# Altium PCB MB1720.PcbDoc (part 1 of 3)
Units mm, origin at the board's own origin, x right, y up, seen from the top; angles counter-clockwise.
Board outline 62.4 x 34.09 mm, 4 copper layers (Top Layer, MidLayer 1, MidLayer 2, Bottom Layer), stack 1.594 mm thick; 82 components, 66 nets, 241 pads, 1258 vias.
Unrouted connection lines stored in the file: 1.
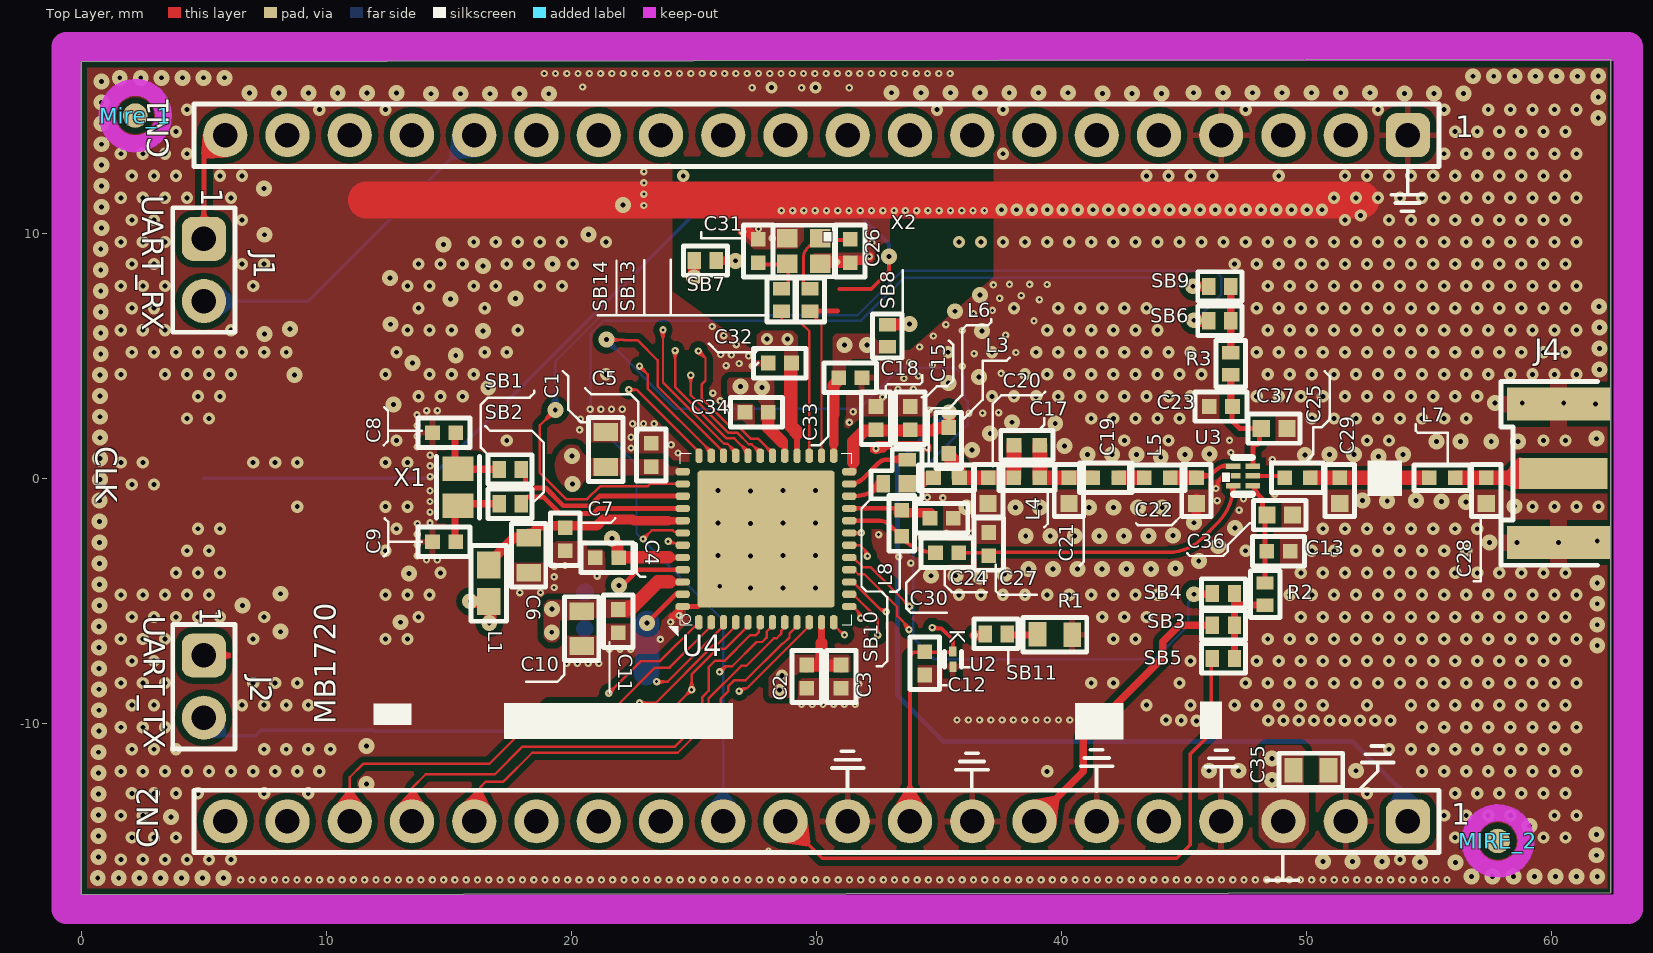
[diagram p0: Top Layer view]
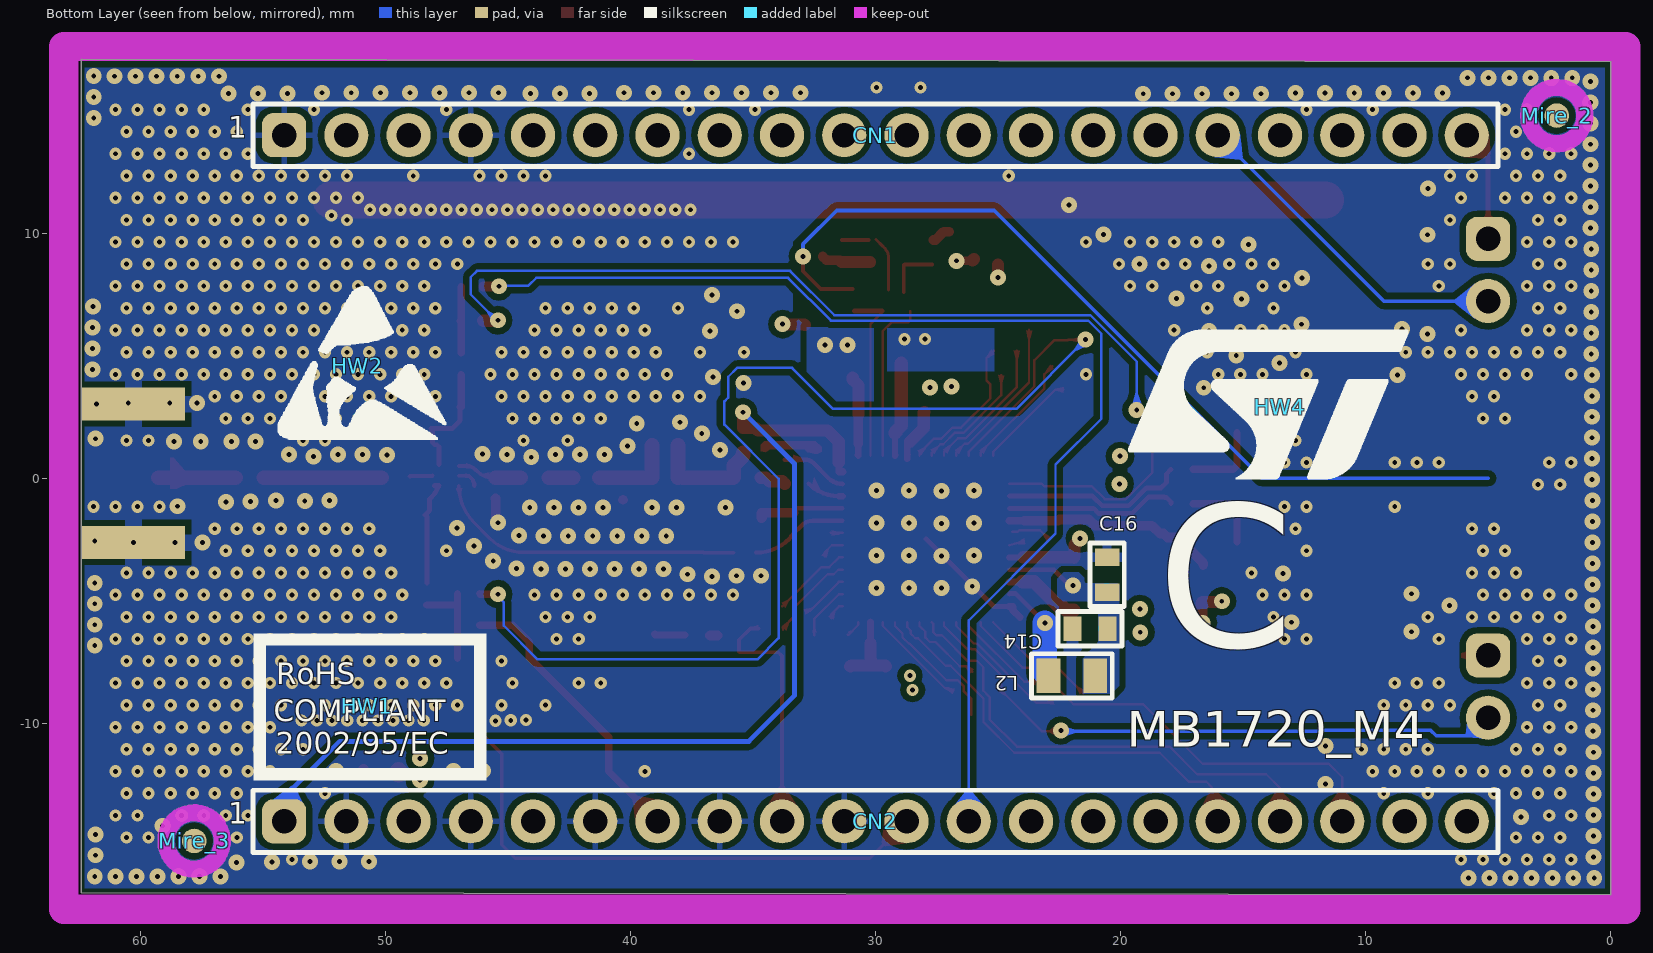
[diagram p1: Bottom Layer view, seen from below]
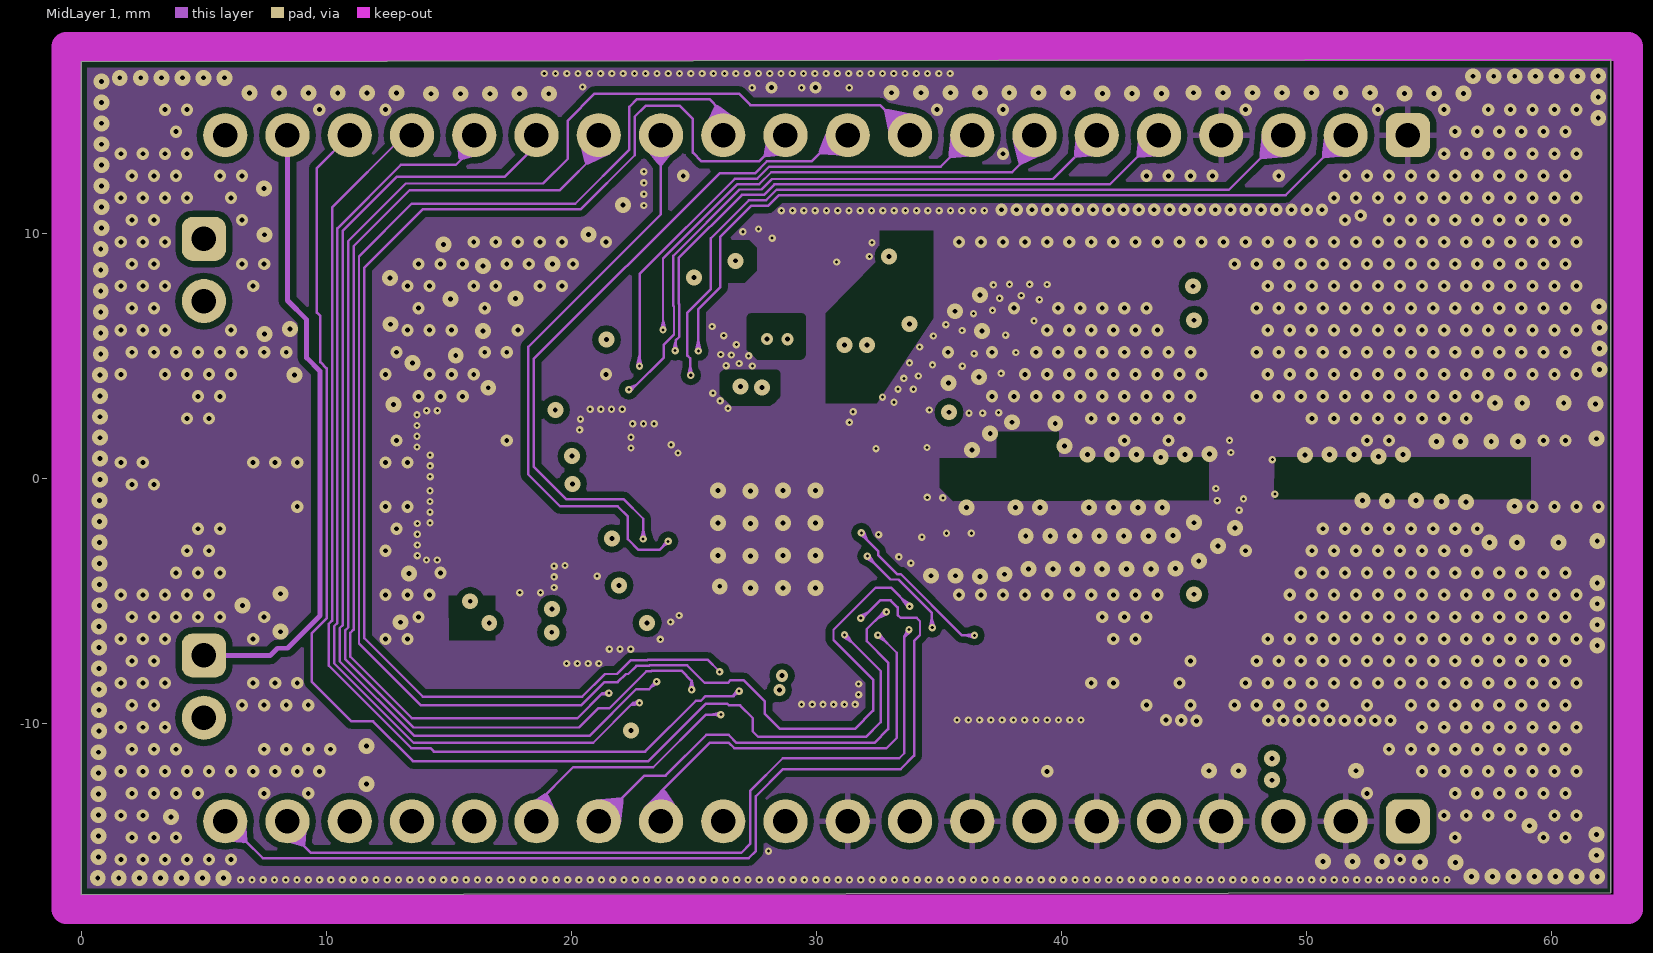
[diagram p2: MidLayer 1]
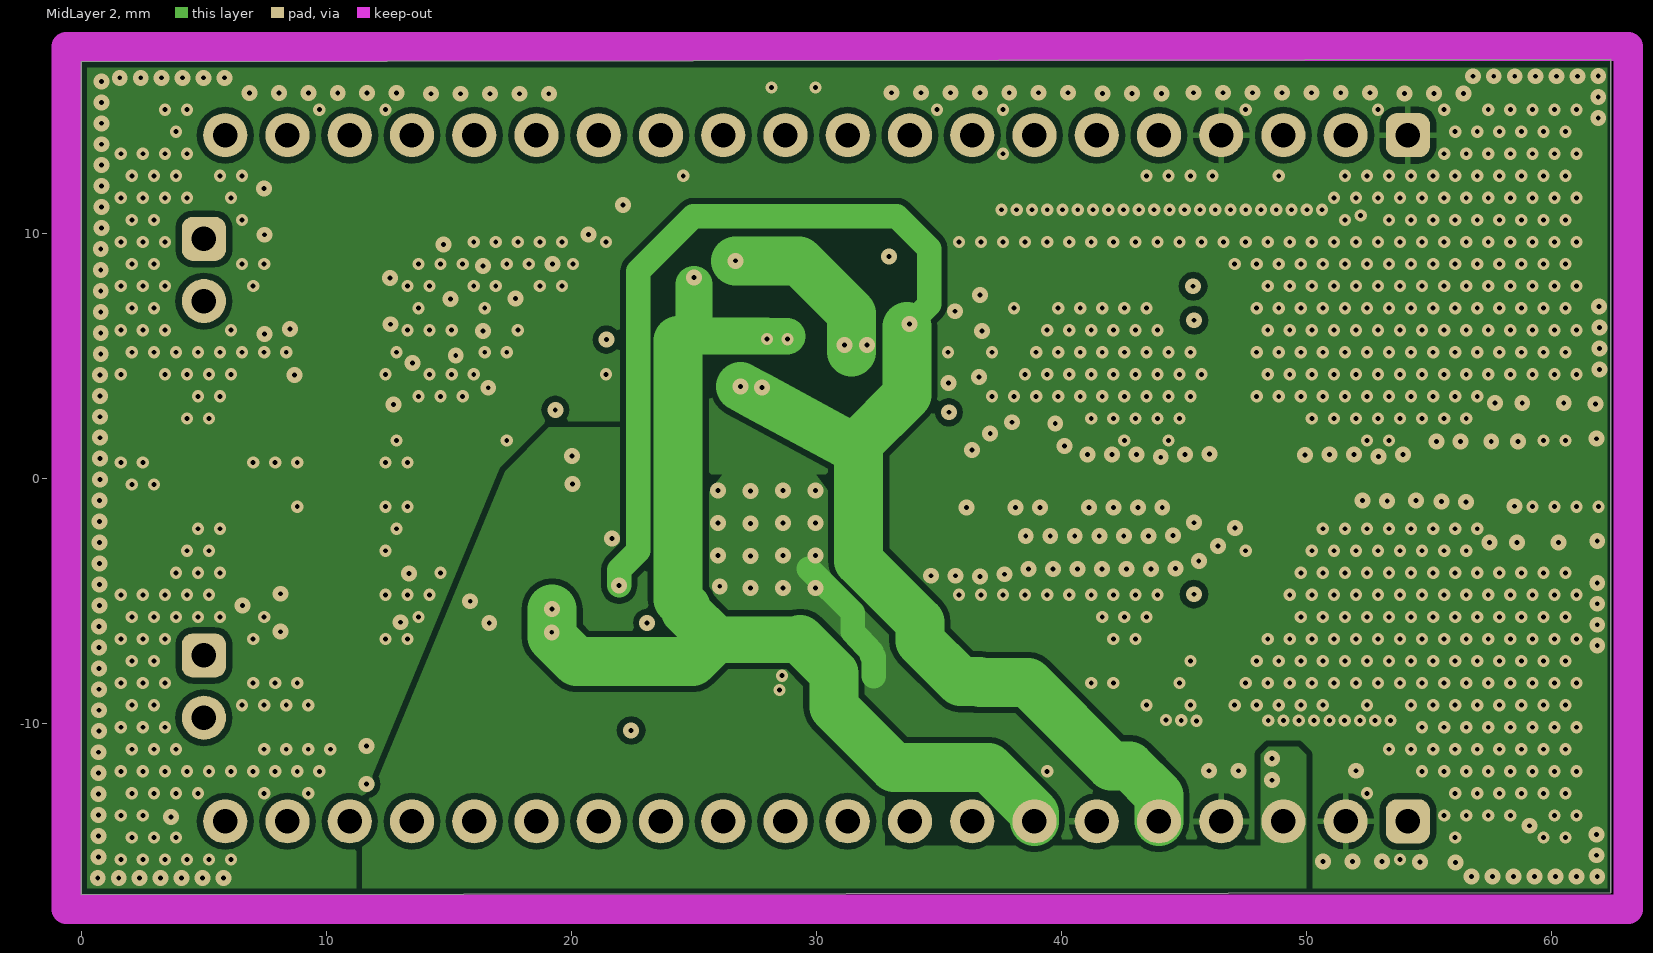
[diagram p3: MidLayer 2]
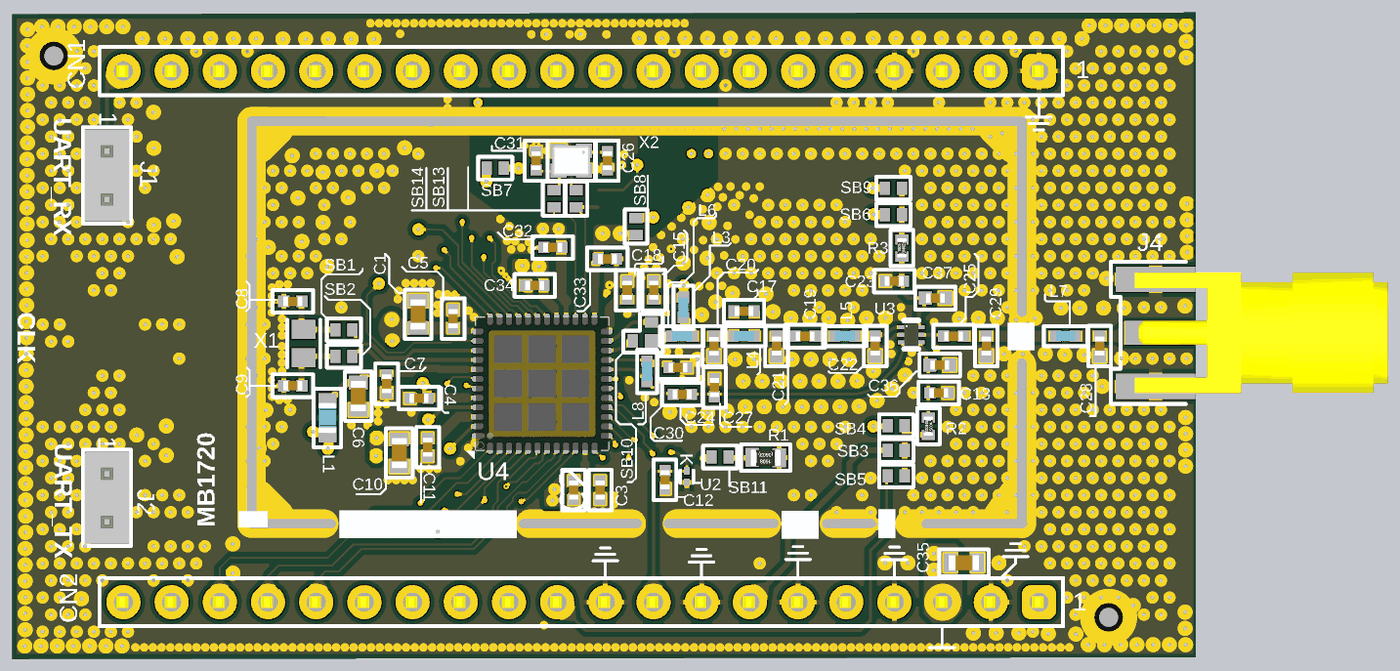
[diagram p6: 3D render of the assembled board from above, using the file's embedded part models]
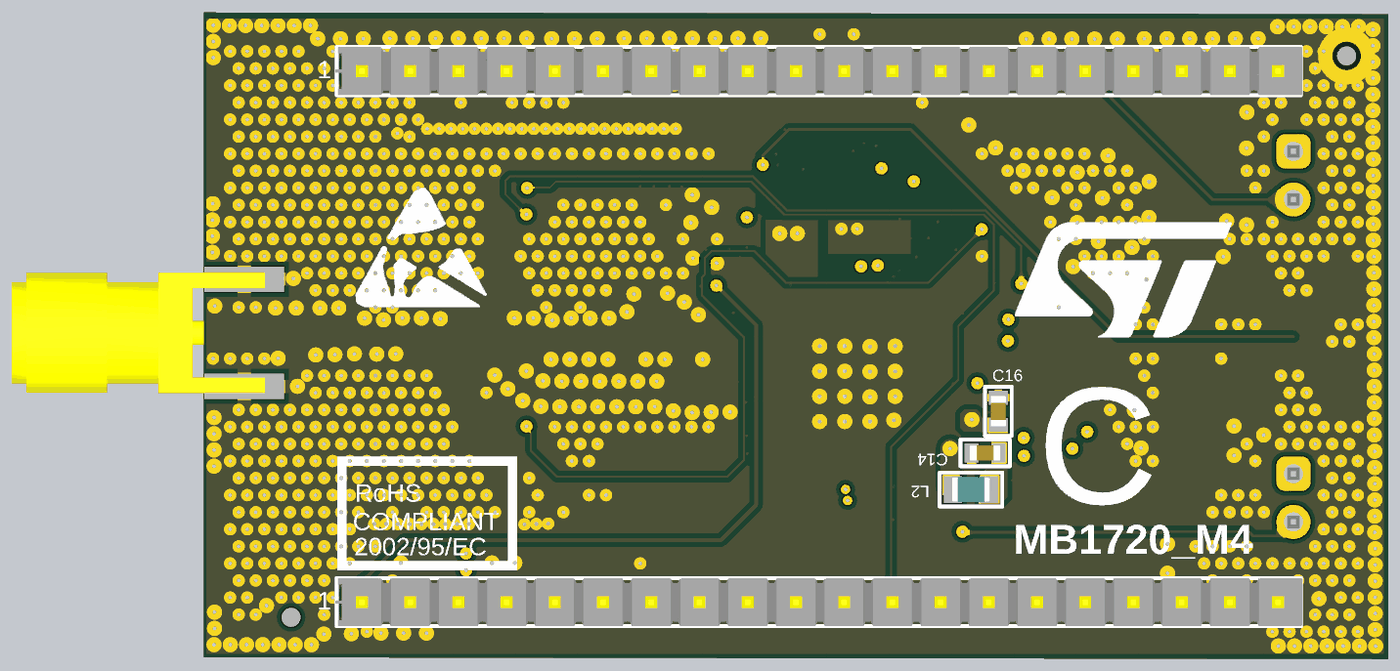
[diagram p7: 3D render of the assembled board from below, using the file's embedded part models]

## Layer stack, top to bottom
Top Solder: solder mask 0.02, Solder Resist, Dk 3.5
Top Layer: signal copper 0.054
Dielectric 1: prepreg 0.108, 1 X 2116, Dk 3.6
MidLayer 1: signal copper 0.035
Dielectric 2: core 1.2, FR4 TG135, Dk 4.7
MidLayer 2: signal copper 0.035
Dielectric 3: prepreg 0.108, 1 X 2116, Dk 3.6
Bottom Layer: signal copper 0.054
Bottom Solder: solder mask 0.02, Solder Resist, Dk 3.5

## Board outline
0,-17 0,17 62.401,17.093 62.401,-16.907

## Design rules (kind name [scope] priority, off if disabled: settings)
BoardOutlineClearance [All] p1 off: gap=0.6 ignorepadtopadclearanceinfootprint=FALSE
Clearance Clearance_2 [InNetClass('50Ohms')] p1: gap=0.19 ignorepadtopadclearanceinfootprint=TRUE except(0.14: SMDPad-Region; 0.15: SMDPad-SMDPad; 0.17: Track-SMDPad; 0.18: Track-Poly)
Clearance Clearance_1 [OnLayer('MidLayer 1')       and InPolygon vs All    and WithinRoom('RoomDefinition_BGA')] p2: gap=0.146 ignorepadtopadclearanceinfootprint=TRUE
Clearance Clearance_tab [(ObjectKind = 'Pad') And (Name Like 'Tab*-*') vs OnLayer('Keep-Out Layer')] p3: gap=0 ignorepadtopadclearanceinfootprint=TRUE
Clearance Clearance_Via_BGA [TouchesRoom('RoomDefinition_BGA') vs isvia or ispad or istrack] p4: gap=0.085 ignorepadtopadclearanceinfootprint=TRUE except(0.15: Arc-Region Track-Region SMDPad-Region THPad-Region Via-Region Region-Region; 0.25: Arc-Fill Arc-Poly Track-Fill Track-Poly SMDPad-Fill SMDPad-Poly THPad-Fill THPad-Poly Via-Fill Via-Poly Fill-Fill Fill-Poly Fill-Region Fill-Text Fill-Hole Poly-Poly Poly-Region Poly-Text Poly-Hole Region-Text Region-Hole)
Clearance Clearance_via_to_via [(ObjectKind = 'Via') And (Net <> 'GND') vs (ObjectKind = 'Via') And (Net <> 'GND')] p5: gap=0.65 ignorepadtopadclearanceinfootprint=TRUE
Clearance "Clearance_Polygon to All" [InPolygon] p6: gap=0.25 ignorepadtopadclearanceinfootprint=TRUE
Clearance [All] p7: gap=0.12 ignorepadtopadclearanceinfootprint=TRUE except(0.25: Arc-Via Track-Via SMDPad-Via THPad-Via Via-Fill Via-Poly Via-Region)
ComponentClearance [All] p1: gap=0 collisioncheckmode=3 verticalgap=0.1 showdistances=FALSE
DiffPairsRouting [InDifferentialPair('RFI')] p1: maxlimit=0.165 minlimit=0.165 mostfreqgap=0.165 toplayer_minwidth=0.08 toplayer_maxwidth=0.4 toplayer_prefwidth=0.145 midlayer1_minwidth=0.145 midlayer1_maxwidth=0.145 midlayer1_prefwidth=0.145 midlayer2_minwidth=0.145 midlayer2_maxwidth=0.145 midlayer2_prefwidth=0.145 bottomlayer_minwidth=0.145 bottomlayer_maxwidth=0.145 bottomlayer_prefwidth=0.145 maxuncoupledlength=12.7
HoleSize [All] p1: absolutevalues=TRUE maxlimit=10 minlimit=0.025 maxpercent=80.000 minpercent=20.000
MaximumViaCount [All] p1: limit=3
MinimumSolderMaskSliver [All] p1: minsoldermaskwidth=0.1
PlaneConnect [InNet('GND')] p1: planeconnectstyle=Relief reliefexpansion=0.508 reliefentries=4 reliefconductorwidth=0.21 reliefairgap=0.21
PolygonConnect PolygonConnect_6 [InNet('VDDRF1V55')] p1: connectstyle=Direct reliefconductorwidth=0.254 reliefentries=4 polygonreliefangle="90 Angle" airgapwidth=0.254
PolygonConnect PolygonConnect_5 [InNet('VDDRF1V55')] p2: connectstyle=Direct reliefconductorwidth=0.254 reliefentries=4 polygonreliefangle="90 Angle" airgapwidth=0.254
PolygonConnect PolygonConnect_4 [InNet('vDDRF')] p3: connectstyle=Direct reliefconductorwidth=0.254 reliefentries=4 polygonreliefangle="90 Angle" airgapwidth=0.254
PolygonConnect PolygonConnect_3 [InNet('VDDPA')] p4: connectstyle=Direct reliefconductorwidth=0.254 reliefentries=4 polygonreliefangle="90 Angle" airgapwidth=0.254
PolygonConnect PolygonConnect_1 [InNet('VDDRF1V55')] p5: connectstyle=Direct reliefconductorwidth=0.254 reliefentries=4 polygonreliefangle="90 Angle" airgapwidth=0.254
PolygonConnect [InNet('VDD')] p6: connectstyle=Direct reliefconductorwidth=0.254 reliefentries=4 polygonreliefangle="90 Angle" airgapwidth=0.254
PolygonConnect PolygonConnect_VRPA [InNet('VRPA')] p7: connectstyle=Direct reliefconductorwidth=0.254 reliefentries=4 polygonreliefangle="90 Angle" airgapwidth=0.254
PolygonConnect PolygonConnect_RF [(ObjectKind = 'Pad') And (Name = 'C30-1')           or (ObjectKind = 'Pad') And (Name = 'C27-1')] p8: connectstyle=Direct reliefconductorwidth=0.254 reliefentries=4 polygonreliefangle="90 Angle" airgapwidth=0.254
PolygonConnect PolygonConnect_J1 [(ObjectKind = 'Pad') And (Name = 'J1-2')] p9: connectstyle=Direct reliefconductorwidth=0.254 reliefentries=4 polygonreliefangle="90 Angle" airgapwidth=0.254
PolygonConnect PolygonConnect_All [All] p10: thpad.connectstyle=Relief thpad.reliefconductorwidth=0.25 thpad.reliefentries=4 thpad.polygonreliefangle="90 Angle" thpad.airgapwidth=0.25 smdpad.connectstyle=Relief smdpad.reliefconductorwidth=0.25 smdpad.reliefentries=4 smdpad.polygonreliefangle="90 Angle" smdpad.airgapwidth=0.25 via.connectstyle=Direct via.reliefconductorwidth=0.2 via.reliefentries=4 via.polygonreliefangle="90 Angle" via.airgapwidth=0.25
RoutingLayers "RoutingLayers_90 Ohms" [InDifferentialPairClass('All Differential Pairs')] p1: top layer_v5=TRUE mid layer 1_v5=TRUE mid layer 2_v5=TRUE bottom layer_v5=TRUE
RoutingLayers [All] p2: top layer_v5=TRUE mid layer 1_v5=TRUE mid layer 2_v5=TRUE bottom layer_v5=TRUE
RoutingVias RoutingVias_BGA [InDrillLayerPair('Top Layer - MidLayer 1')] p1: holewidth=0.125 width=0.25 viastyle="Through Hole" minholewidth=0.125 minwidth=0.25 maxholewidth=0.125 maxwidth=0.3
RoutingVias [All] p2: holewidth=0.2 width=0.65 viastyle="Through Hole" minholewidth=0.2 minwidth=0.5 maxholewidth=0.2 maxwidth=0.65
ShortCircuit [(ObjectKind = 'Via') And (DrillPair = 'Top Layer - MidLayer 1') vs Ispad] p1: allowed=TRUE
SilkToSilkClearance [All] p1: silktosilkclearance=0.2
SilkToSolderMaskClearance [IsPad] p1: minsilkscreentomaskgap=0.2 clearancetoexposedcopper=TRUE
SolderMaskExpansion SolderMaskExpansion_VIA [IsVia] p1: expansion=-0.2 istentingtop=FALSE
SolderMaskExpansion [All] p2: expansion=0.075 istentingtop=FALSE
Width Width_BGA [OnLayer('Top Layer')      and WithinRoom('RoomDefinition_BGA')] p1: maxlimit=0.08 minlimit=0.08 preferedwidth=0.08 minimp=50.000000 maximp=50.000000 favimp=50.000000
Width Width_50Ohms [InNetClass('50Ohms')] p2: maxlimit=0.7 minlimit=0.097 preferedwidth=0.5 toplayer_minwidth=0.14 midlayer1_maxwidth=0.5 midlayer2_minwidth=0.2 midlayer2_maxwidth=0.5 bottomlayer_minwidth=0.2 bottomlayer_maxwidth=0.5 minimp=50.000000 maximp=50.000000 favimp=50.000000
Width [All] p3: maxlimit=2 minlimit=0.08 preferedwidth=0.15 toplayer_minwidth=0.097 toplayer_maxwidth=1.5 midlayer1_maxwidth=1 midlayer2_minwidth=0.1 bottomlayer_minwidth=0.1 bottomlayer_maxwidth=1.5 minimp=50.000000 maximp=50.000000 favimp=50.000000
21 further rules are at their usual default settings.

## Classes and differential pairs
net class 50Ohms: NetC17_1 NetC17_2 NetC19_1 NetC22_2 NetC24_2 NetC25_1 NetC25_2 NetC28_1 NetL6_2 NetSB10_1 NetSB10_3
component class BEE_UFQFPN48_Ref_Board: C1 C2 C3 C4 C5 C6 C7 C8 C9 C10 C11 C12 C13 C14 C15 C16 C17 C18 C19 C20 C21 C22 C23 C24 C25 C26 C27 C28 C29 C30 C31 C32 C33 C34 C35 C36 C37 CN1 CN2 J1 J2 J4 L1 L2 L3 L4 L5 L6 L7 L8 R1 R2 R3 SB1 SB2 SB3 SB4 SB5 SB6 SB7 SB8 SB9 SB10 SB11 SB13 SB14 U2 U3 U4 X1 X2
differential pair RFI: +RFI_P -RFI_N

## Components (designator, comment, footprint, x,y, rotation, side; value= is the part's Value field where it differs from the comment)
C1 "" CAPC1608X09N 21.4,1.175 r270 top value=4.7uF
C2 "" CAPC1005X06N 29.6,-8.09 r90 top value=100nF
C3 "" CAPC1005X06N 31,-8.09 r90 top value=100nF
C4 "" CAPC1005X06N 21.449,-3.241 r0 top value=100nF
C5 "" CAPC1005X06N 23.251,0.95 r270 top value=100nF
C6 "" CAPC1608X09N 18.249,-3.139 r270 top value=4.7uF
C7 "" CAPC1005X06N 19.749,-2.488 r270 top value=100nF
C8 "Capacitor" CAPC1005X06N 14.798,1.862 r180 top value=6.8pF
C9 "Capacitor" CAPC1005X06N 14.798,-2.589 r180 top value=6.8pF
C10 "" CAPC1608X09N 20.411,-6.134 r270 top value=4.7uF
C11 "" CAPC1005X06N 21.911,-5.832 r270 top value=100nF
C12 "" CAPC1005X06N 34.413,-7.549 r270 top value=100nF
C13 "" CAPC1005X06N 48.847,-2.973 r180 top value=1nF
C14 "" CAPC1608X09N 21.243,-6.136 r0 bottom value="0.47 uF"
C15 "" CAPC1005X06N 33.823,2.45 r90 top value="47 nF"
C16 "" CAPC1608X09N 20.546,-3.936 r90 bottom value="100 nF"
C17 "" "CAPC1005X06N - DUPLICATE - DUPLICATE"#1 38.581,1.345 r0 top value="3.6 pF"
C18 "" CAPC1005X06N 32.423,2.45 r270 top value="68 pF"
C19 "" "CAPC1005X06N - DUPLICATE - DUPLICATE"#1 41.799,0.025 r180 top value="68 pF"
C20 "" "CAPC1005X06N - DUPLICATE - DUPLICATE"#2 37,-0.505 r270 top value=N/C
C21 "" "CAPC1005X06N - DUPLICATE - DUPLICATE"#3 40.299,-0.5 r90 top value="15 pF"
C22 "" "CAPC1005X06N - DUPLICATE - DUPLICATE"#3 45.5,-0.5 r90 top value="5.6 pF"
C23 "" CAPC1005X06N 46.5,2.926 r0 top value=1nF
C24 "" CAPC1005X06N 35.325,-3.035 r0 top value=3.6pF
C25 "" "CAPC1005X06N - duplicate - duplicate"#1 49.625,0.025 r0 top value=33pF
C26 "Capacitor" CAPC1005X06N 31.375,9.275 r270 top value=6.8pF
C27 "NC" CAPC1005X06N 37.025,-2.686 r270 top value=(0402)
C28 "" "CAPC1005X06N - DUPLICATE - DUPLICATE"#2 57.325,-0.5 r270 top value=3.3pF
C29 "" "CAPC1005X06N - DUPLICATE - DUPLICATE"#2 51.35,-0.5 r270 top value=3.3pF
C30 "" CAPC1005X06N 35.1,-1.635 r180 top value=2.7pF
C31 "Capacitor" CAPC1005X06N 27.625,9.275 r90 top value=6.8pF
C32 "" CAPC1005X06N 28.5,4.7 r0 top value=33pF
C33 "" CAPC1005X06N 31.375,4.1 r180 top value=33pF
C34 "" CAPC1005X06N 27.55,2.7 r0 top value=33pF
C35 "" CAPC1608X09N 50.171,-11.918 r0 top value=4.7uF
C36 "Capa_0402" "CAPC1005X06N - duplicate - duplicate"#2 48.901,-1.5 r180 top value="10 pF"
C37 "Capa_0402" "CAPC1005X06N - duplicate - duplicate"#2 48.667,2.031 r180 top value="10 pF"
CN1 "CON20" CO_SAMTEC_TSW-120-07-X-S 30,14 r180 bottom
CN2 "CON20" CO_SAMTEC_TSW-120-07-X-S 30,-14 r180 bottom
Designator1 "Comment" PCB_SPECIFICATIONS -0.35,22.461 r0 top
Designator1 "Comment" Sheetbox_4L2S -0.909,-48.691 r0 top
Designator16 "Comment" IMPEDANCE_TABLE -0.509,60.799 r0 top
HW1 "Logo" LOGO_ROHS 50.75,-9.3 r180 bottom value="LOGO ROHS"
HW2 "Logo" LOGO_MAIN 51.15,4.6 r180 bottom value="LOGO ESD"
HW4 "Logo" LOGO_ST 13.5,2.9 r180 bottom value="LOGO ST"
J1 "HEADER_1X2_L" CO_MOLEX_22-03-2021 5,8.5 r270 top
J2 "HEADER_1X2_L" CO_MOLEX_22-03-2021 5,-8.5 r270 top
J4 "SMA_T_9.52_NF" CO_SAMTEC_SMA-J-P-ST-EMI 62.37,0.2 r90 top locked
L1 "" INDC1608X95N 16.624,-4.286 r90 top value=600R@100MHz
L2 "" INDC2012X13N 21.985,-8.061 r0 bottom value=15µH
L3 "" IND_MURATA_LQW15A 35.388,1.545 r90 top value="68 nH"
L4 "" IND_MURATA_LQW15A 38.581,0.02 r0 top value="8.2 nH"
L5 "" IND_MURATA_LQW15A 43.9,0.025 r0 top value="18 nH"
L6 "" IND_MURATA_LQW15A 35.298,0.019 r180 top value="0 Ohm"
L7 "" IND_MURATA_LQW15A 55.525,0.025 r0 top value=8.7nH
L8 "" IND_MURATA_LQW15A 33.475,-1.835 r90 top value=11nH
M1 "Comment" "MIRE PCB" 80,-2 r0 top locked
Mire_1 "Comment" MIRE#1 2.2,14.8 r0 top
MIRE_2 "Comment" MIRE#1 57.8,-14.8 r0 top
Mire_2 "Comment" MIRE#1 2.2,14.8 r180 bottom
Mire_3 "Comment" MIRE#2 57.8,-14.8 r180 bottom
R1 "" RESC1608X05N 39.723,-6.381 r180 top value=10K
R2 "" RESC1005X04N 48.303,-4.723 r270 top value=100R
R3 "" RESC1005X04N 46.9,4.676 r90 top value=100R
SB1 "Close" SB_0402 17.493,0.362 r180 top value=0
SB2 "Close" SB_0402 17.493,-1.039 r180 top value=0
SB3 "Close" SB_0402 46.603,-5.999 r0 top value=0
SB4 "Open" SB_0402 46.603,-4.699 r0 top
SB5 "Open" SB_0402 46.603,-7.348 r0 top
SB6 "Close" SB_0402 46.454,6.426 r0 top value=0
SB7 "Open" SB_0402 25.465,8.885 r180 top
SB8 "Close" SB_0402 32.887,5.808 r270 top value=0
SB9 "Open" SB_0402 46.454,7.826 r0 top
SB10 "SB_3Pads" SB3PADS_0402 33.689,0.292 r90 top
SB11 "Close" SB_0402 37.323,-6.349 r180 top value="0 ohm"
SB13 "Close" SB_0402 29.725,7.275 r90 top value=0
SB14 "Close" SB_0402 28.575,7.275 r90 top value=0
U2 "" DIOM0603X03N 35.563,-7.382 r270 top
U3 "BGS12SN6" SON40P70X40-6N 47.4,0.1 r0 top locked
U4 "STM32WLxx_QFN48" STM32WLXX_QFN48 27.94,-2.479 r90 top locked
X1 "XTAL_2_PINS" OSC_NDK_NX2012SA 15.368,-0.364 r90 top value=32.768KHz
X2 "" OSC_NDK_NX2016SA 29.475,9.275 r180 top value=32MHz

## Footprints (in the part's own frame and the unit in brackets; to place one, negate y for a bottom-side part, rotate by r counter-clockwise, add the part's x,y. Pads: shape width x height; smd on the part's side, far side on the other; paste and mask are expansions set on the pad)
CAPC1005X06N [mm] "Chip Capacitor, 2-Leads, Body 1.00x0.70x0.70mm (0402)"
  rect 0.6x0.6 smd: 1(-0.475,0) 2(0.475,0)
  silkscreen extent -1.07,-0.6 1.07,0.6, body extent -0.5,-0.25 0.5,0.25, height 0.6
"CAPC1005X06N - DUPLICATE - DUPLICATE"#1 [mm] "Chip Capacitor, 2-Leads, Body 1.00x0.70x0.70mm (0402)"
  rect 0.6x0.6 smd: 1(-0.525,0) 2(0.525,0)
  silkscreen extent -1.07,-0.6 1.07,0.6, body extent -0.5,-0.25 0.5,0.25, height 0.6
"CAPC1005X06N - DUPLICATE - DUPLICATE"#2 [mm] "Chip Capacitor, 2-Leads, Body 1.00x0.70x0.70mm (0402)"
  rect 0.6x0.6 smd: 1(-0.525,0)
  rect 0.7x0.7 smd: 2(0.525,0)
  silkscreen extent -1.07,-0.6 1.07,0.6, body extent -0.5,-0.25 0.5,0.25, height 0.6
"CAPC1005X06N - DUPLICATE - DUPLICATE"#3 [mm] "Chip Capacitor, 2-Leads, Body 1.00x0.70x0.70mm (0402)"
  rect 0.7x0.7 smd: 1(-0.525,0)
  rect 0.6x0.6 smd: 2(0.525,0)
  silkscreen extent -1.07,-0.6 1.07,0.6, body extent -0.5,-0.25 0.5,0.25, height 0.6
"CAPC1005X06N - duplicate - duplicate"#1 [mm] "Chip Capacitor, 2-Leads, Body 1.00x0.70x0.70mm (0402)"
  rect 0.6x0.6 smd: 1(-0.525,0) 2(0.525,0)
  silkscreen extent -1.07,-0.6 1.07,0.6, body extent -0.5,-0.25 0.5,0.25, height 0.6
"CAPC1005X06N - duplicate - duplicate"#2 [mm] "Chip Capacitor, 2-Leads, Body 1.00x0.70x0.70mm (0402)"
  rect 0.7x0.7 smd: 1(-0.525,0) 2(0.525,0)
  silkscreen extent -1.07,-0.6 1.07,0.6, body extent -0.5,-0.25 0.5,0.25, height 0.6
CAPC1608X09N [mm] "Chip Capacitor, 2-Leads, Body 1.60x0.80x0.90mm (0603)"
  rect 0.725x1 smd: 1(-0.713,0) 2(0.713,0)
  Top Layer pour cut-out: -0.3,0.7 0.3,0.7 0.3,-0.7 -0.3,-0.7
  silkscreen extent -1.3,-0.7 1.3,0.7, body extent -0.8,-0.4 0.8,0.4, height 0.9
CO_MOLEX_22-03-2021 [mm]
  rrect50% 1.8x1.8 hole 1: 1(-1.27,0)
  round 1.8 hole 1: 2(1.27,0)
  silkscreen extent -2.54,-1.27 2.54,1.27, body extent -2.41,-1.18 2.41,1.18, height 10.79
CO_SAMTEC_SMA-J-P-ST-EMI [mm] "SMA Jack CMS, Edge Mountt Receptacle 50Ohm, 5-Leads, Body 6.35x6.35x9.52mm, pitch 2.825mm"
  rect 1.27x3.6 smd mask+0.05: 1(0,1.9)
  rect 1.35x4.2 smd mask+0.05: 2(-2.825,2.1) 2(2.825,2.1)
  rect 1.35x4.2 smd far side mask+0.05: 2(-2.825,2.1) 2(2.825,2.1)
  silkscreen extent -3.75,0.5 3.75,4.45, body extent -3.17,-10.13 3.17,3.2, height 3.8
CO_SAMTEC_TSW-120-07-X-S [mm] "Header, 20-Leads, 50.80x2.54x10.80mm, Pitch 2.54mm"
  rrect50% 1.8x1.8 hole 1: 1(-24.13,0)
  round 1.8 hole 1: 2(-21.59,0) 3(-19.05,0) 4(-16.51,0) 5(-13.97,0) 6(-11.43,0) 7(-8.89,0) 8(-6.35,0) 9(-3.81,0) 10(-1.27,0) 11(1.27,0) 12(3.81,0) 13(6.35,0) 14(8.89,0) 15(11.43,0) 16(13.97,0) 17(16.51,0) 18(19.05,0) 19(21.59,0) 20(24.13,0)
  silkscreen extent -25.4,-1.27 25.4,1.27, body extent -25.46,-1.27 25.46,1.27, height 8.38
DIOM0603X03N [mm] "Molded Diode, 2-Leads, Body 0.60x0.30mm"
  rect 0.425x0.3 smd: 1(-0.313,0) 2(0.313,0)
  silkscreen extent -0.33,-0.35 0.33,0.35, body extent -0.32,-0.18 0.33,0.18, height 0.33
IMPEDANCE_TABLE [mm]
IND_MURATA_LQW15A [mm] "Inductor 2-Leads,Body 1.10x0.70x0.60mm(max)"
  rect 0.6x0.6 smd: 1(-0.53,0) 2(0.53,0)
  silkscreen extent -1.14,-0.53 1.14,0.53, body extent -0.5,-0.3 0.5,0.3, height 0.51
INDC1608X95N [mm] "Chip Inductor, 2-Leads, Body 1.75x0.95x0.95mm (0603)"
  rect 1.1x0.95 smd: 1(-0.75,0) 2(0.75,0)
  silkscreen extent -1.55,-0.72 1.55,0.72, body extent -0.8,-0.48 0.8,0.47, height 0.8
INDC2012X13N [mm] "Chip Inductor, 2-Leads, Body 2.0x1.2x1.3 (0805)"
  rect 0.96x1.4 smd: 1(-0.952,0) 2(0.952,0)
  silkscreen extent -1.65,-0.9 1.65,0.9, body extent -1,-0.65 1,0.65, height 1.18
LOGO_MAIN [mm]
  silkscreen extent -3.24,-3.02 3.65,3.22
LOGO_ROHS [mm]
  silkscreen extent -4.63,-3.03 4.87,2.98
LOGO_ST [mm]
  silkscreen extent -6.18,-2.95 5.25,3.14
MIRE#1 [mm] "Fiducial Target Round , Pad 1.0mm, Keepout 3mm"
  round 1 smd mask+1: 1(0,0)
  Top Layer keep-out circle w0.7: c0,0 r1.15
  body extent -0.5,-0.5 0.5,0.5, height 0.04
MIRE#2 [mm] "Fiducial Target Round , Pad 1.0mm, Keepout 3mm"
  round 1 smd: 1(0,0)
  Top Layer keep-out circle w0.7: c0,0 r1.15
  body extent -0.5,-0.5 0.5,0.5, height 0.04
"MIRE PCB" [mm]
OSC_NDK_NX2012SA [mm] "Crystal, 2-Leads, Body 2.05x1.20x0.55mm (Tol:-/+0.05)"
  rect 1x1.25 smd: 1(-0.75,0) 2(0.75,0)
  silkscreen extent -1.25,-0.87 1.25,0.87, body extent -1.04,-0.63 1.03,0.63, height 0.55
OSC_NDK_NX2016SA [mm] "Crystal, 4-Leads, Body 2.10x1.61x0.50mm (max), Pitch 1.35x1.05mm"
  rect 0.85x0.75 smd: 1(-0.675,-0.525) 2(0.675,-0.525) 3(0.675,0.525) 4(-0.675,0.525)
  silkscreen extent -1.25,-1.05 1.25,1.05, body extent -1,-0.8 1,0.8, height 0.5
PCB_SPECIFICATIONS [mm]
RESC1005X04N [mm] "Chip Resistor, 2-Leads, Body 1.00x0.50mm (0402)"
  rect 0.55x0.7 smd: 1(-0.45,0) 2(0.45,0)
  silkscreen extent -0.95,-0.6 0.95,0.6, body extent -0.5,-0.25 0.5,0.25, height 0.35
RESC1608X05N [mm] "Chip Resistor, 2-Leads, Body 1.60x0.80mm (0603)"
  rect 0.725x1 smd: 1(-0.713,0) 2(0.712,-0.016)
  Top Layer pour cut-out: -0.3,0.7 0.3,0.7 0.3,-0.7 -0.3,-0.7
  silkscreen extent -1.3,-0.7 1.3,0.7, body extent -0.77,-0.42 0.78,0.43, height 0.45
SB3PADS_0402 [mm] "Solder Bridge 0 Ohm (0402)"
  rect 0.55x0.7 smd: 1(0.466,-0.009)
  rect 0.7x0.7 smd: 2(-0.517,-0.009)
  rect 0.7x0.55 smd: 3(-0.517,0.974)
  silkscreen extent -1.13,-0.61 0.91,1.46, body extent -0.79,-0.05 -0.29,0.95, height 0.25
SB_0402 [mm] "Solder Bridge 0 Ohm (0402)"
  rect 0.55x0.7 smd: 1(-0.45,0) 2(0.45,0)
  silkscreen extent -0.9,-0.6 0.9,0.6, body extent -0.5,-0.25 0.5,0.25, height 0.25
Sheetbox_4L2S [mil] "Sheetbox 4 layers / 2 silkscreens"
  round 20 on Mech16: 1(813.78,210.69) 1(2736.9,210.69)
SON40P70X40-6N [mm] "SON, 6-Leads, Body 1.10x0.70mm, Pitch 0.40mm"
  rect 0.6x0.225 smd: 1(-0.4,0.4) 2(-0.4,0) 3(-0.4,-0.4) 4(0.4,-0.4) 5(0.4,0) 6(0.4,0.4)
  silkscreen extent -0.38,-0.75 0.38,0.75, body extent -0.38,-0.58 0.38,0.58, height 0.4
STM32WLXX_QFN48 [mm] "QFN48 7x7x0.55mm pitch 0.5mm"
  oct 0.6x0.3 smd mask+0.06: 1(-3.398,2.746) 2(-3.398,2.239) 3(-3.398,1.739) 4(-3.398,1.239) 5(-3.398,0.739) 6(-3.398,0.239) 7(-3.398,-0.261) 8(-3.398,-0.761) 9(-3.398,-1.261) 10(-3.398,-1.761) 11(-3.398,-2.261) 12(-3.398,-2.761) 25(3.398,-2.761) 26(3.398,-2.261) 27(3.398,-1.761) 28(3.398,-1.261) 29(3.398,-0.761) 30(3.398,-0.261) 31(3.398,0.239) 32(3.398,0.739) 33(3.398,1.239) 34(3.398,1.739) 35(3.398,2.239) 36(3.398,2.739)
  oct 0.3x0.6 smd mask+0.06: 13(-2.752,-3.399) 14(-2.252,-3.399) 15(-1.752,-3.399) 16(-1.252,-3.399) 17(-0.752,-3.399) 18(-0.252,-3.399) 19(0.248,-3.399) 20(0.748,-3.399) 21(1.248,-3.399) 22(1.748,-3.399) 23(2.248,-3.399) 24(2.748,-3.399) 37(2.748,3.399) 38(2.248,3.399) 39(1.748,3.399) 40(1.248,3.399) 41(0.748,3.399) 42(0.248,3.399) 43(-0.252,3.399) 44(-0.752,3.399) 45(-1.252,3.399) 46(-1.752,3.399) 47(-2.252,3.399) 48(-2.752,3.399)
  rrect5% 5.6x5.6 smd paste-3 mask+0.08: 49(0,0)
  silkscreen extent -3.95,-3.5 3.5,3.96, body extent -3.51,-3.51 3.51,3.51, height 0.78

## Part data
C1 C6 C10 C35: library part MCD-00009, "Capacitor, MLCC, 4.7uF, 16V, X5R, 10%, 0603, T=0.8mm", Manufacturer=YAGEO, Manufacturer_Part_Number=CC0603KRX5R7BB475, Package=C0603
C2 C3 C4 C5 C7 C11 C12: library part MCD-00102, "Capacitor, MLCC, 100nF, 16V, X7R, 10%, 0402, T=0,5mm", Manufacturer=YAGEO, Manufacturer_Part_Number=CC0402KRX7R7BB104, Package=C0402
C8 C9 C26 C31: library part MCD-00003, "Capacitor, MLCC, 6.8pF, 50V, NPO, +-0.1pF, 0402, T=0.5mm", Manufacturer=MURATA, Manufacturer_Part_Number=GRM1555C1H6R8BA01
C13 C23: library part MCD-00198, "Capacitor, MLCC, 1nF, 16V, X7R, 10%, 0402, T=0.5mm", Manufacturer=YAGEO, Manufacturer_Part_Number=CC0402KRX7R7BB102
C14: library part MCD-00009, "Capacitor, MLCC, 4.7 uF, 16V, X5R, 10%, 0603, T=0.8mm", Manufacturer=YAGEO, Manufacturer_Part_Number=CC0603KRX5R7BB474, Package=C0603
C15: library part MCD-01123, Manufacturer=MURATA, Manufacturer_Part_Number=GCM155R71E473KA55
C16: library part MCD-00009, "Capacitor, MLCC, 100 nF, 16V, X5R, 10%, 0603, T=0.8mm", Manufacturer=YAGEO, Package=C0603
C17: library part MCD-01123, Manufacturer=MURATA, Manufacturer_Part_Number=GJM1555C1H3R6CB01
C18: library part MCD-01123, Manufacturer=MURATA, Manufacturer_Part_Number=GCM1555C1H680JA16
C19: library part MCD-01123, Manufacturer=muRata, Manufacturer_Part_Number=GJM1555C1H680JA01
C20: library part MCD-00102, "N/C", Manufacturer=Murata, Manufacturer_Part_Number="Not Connected", Package=C0402
C21: library part MCD-00015, Manufacturer=MURATA, Manufacturer_Part_Number=GJM1555C1H150JB01
C22: library part MCD-01123, Manufacturer=muRata, Manufacturer_Part_Number=GJM1555C1H5R6DB01
C24: library part MCD-01123, Manufacturer=MURATA, Manufacturer_Part_Number=GJM1555C1H3R6WB01D
C25: library part MCD-01123, "Condensateurs céramique multicouches MLCC - CMS 33PF 50V 2% 0402", Manufacturer=Murata, Manufacturer_Part_Number=GJM1555C1H330GB01D
C27: library part MCD-01123, "Not connected [0402]", Manufacturer=MURATA
C28: library part Capacitor, Manufacturer=Murata, Manufacturer_Part_Number=GJM1555C1H3R3WB01D, Package=C0402
C29: library part MCD-00102, Manufacturer=Murata, Manufacturer_Part_Number=GJM1555C1H3R3WB01D, Package=C0402
C30: library part MCD-01123, Manufacturer=MURATA, Manufacturer_Part_Number=GJM1555C1H2R7BB01D
C32 C33 C34: library part MCD-00277, "Capacitor, MLCC, 33pF, 50V, NPO, 2%, 0402, T=0,5mm", Manufacturer=MURATA, Manufacturer_Part_Number=GRM1555C1H330GA01
C36 C37: "10pF ±1% 50V Ceramic Capacitor C0G, NP0 0402 (1005 Metric)", Manufacturer=MURATA, Manufacturer_Part_Number=GJM1555C1H100FB01D
CN1 CN2: "Connector right-angle, pitch 2.54mm, 20 contacts", Manufacturer=SAMTEC, Manufacturer_Part_Number=TSW-120-07-L-S
Designator16: library part MCD-00279
HW1: library part MCD-00628, "\"ROHS\" logo footprint for PCB"
HW2: library part MCD-00627, "\"Hand\" ESD logo footprint for PCB"
HW4: library part MCD-00625, "\"STMicroelectronics\" logo footprint for PCB"
J1 J2: "Header 1x2 Through hole 2.54mm", Manufacturer=MOLEX, Manufacturer_Part_Number=22-03-2021
J4: "SMA Jack, Edge Mount, 50 Ohms", Manufacturer=SAMTEC, Manufacturer_Part_Number=SMA-J-P-H-ST-EM1
L1: library part MCD-00047, "SMD Chip ferrite bead, 600R@100MHz +/-25%, 350mA, 500mohm DC, 0603, T=0.8mm", Manufacturer=TAI-TECH, Manufacturer_Part_Number=FCM1608KF-601T03
L2: library part MCD-01433, "MLZ2012 Multilayer Shielded Inductor 15µH, ±5%", Manufacturer=TDK, Manufacturer_Part_Number=MLZ2012M150W
L3: library part MCD-01330, "Inductor, 68nH, +-0.1nH, 140mA, 0402", Manufacturer=MURATA, Manufacturer_Part_Number=LQW15AN68NG00
L4: library part MCD-01330, Manufacturer=muRata, Manufacturer_Part_Number=LQW15AN8N2G00
L5: library part MCD-01330, Manufacturer=muRata, Manufacturer_Part_Number=LQW15AN18NG00
L6: library part MCD-01330, "Résistance 0 ohm", Manufacturer="Vishay / Dale", Manufacturer_Part_Number=RCS04020000Z0ED
L7: library part MCD-01330, Manufacturer=MURATA, Manufacturer_Part_Number=LQW15AN15NG00
L8: library part MCD-01330, Manufacturer=MURATA, Manufacturer_Part_Number=LQW15AN11NG00D
R1: library part MCD-00220, "Resistor,10K,0603,1%,1/10W", Manufacturer=YAGEO, Manufacturer_Part_Number=RC0603FR-0710KL
R2 R3: library part MCD-00119, "Resistor,100R,0402,1%,1/16W", Manufacturer=YAGEO, Manufacturer_Part_Number=RC0402FR-07100RL
SB1 SB2 SB3 SB6 SB8 SB11 SB13 SB14: library part SB_0Ohm, "Solder Bridge 0R [0402] (Populated with 0 Ohm)", Manufacturer="Vishay / Dale", Manufacturer_Part_Number=RCS04020000Z0ED
SB4 SB5 SB7 SB9: library part SB_Open, "Solder Bridge Open [0402] (Unpopulated)"
SB10: "Solder Bridge"
U2: library part MCD-00170, "ESD protection 6V1", Manufacturer=STMICROELECTRONICS, Manufacturer_Part_Number=ESDALC6V1-1U2
U3: "DC switch - Ultra-Low  SPDT analog switch", Manufacturer=INFINEON
U4: "HQDC : Verified April, 25 2019"
X1: library part MCD-01479, "Crystal 32.768kHz, 6pF, -+20PPM, R=80K, SMD", Manufacturer=NDK, Manufacturer_Part_Number="NX2012SA 32.768KHz EXS00A-MU00527"
X2: library part MCD-01446, "Crystal 32 MHz, 8pF, -+10 PPM, R=60Ω, SMD", Manufacturer=NDK, Manufacturer_Part_Number="NX2016SA 32MHz EXS00A-CS06465"

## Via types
v1: diameter 0.5, hole 0.2, Top Layer to Bottom Layer, 667 vias
v2: diameter 0.3, hole 0.125, Top Layer to MidLayer 1, 336 vias
v3: diameter 0.65, hole 0.2, Top Layer to Bottom Layer, 255 vias

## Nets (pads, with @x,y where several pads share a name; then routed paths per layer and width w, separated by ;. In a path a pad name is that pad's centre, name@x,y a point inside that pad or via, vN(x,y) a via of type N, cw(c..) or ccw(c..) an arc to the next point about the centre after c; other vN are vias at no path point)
FE_CTRL2: CN2.12 SB9.1 | length 48.5
  Top Layer w0.4: v3(45.367,7.835) 45.371,7.831 46,7.831 SB9.1@46.004,7.826
  Bottom Layer w0.1: CN2.12@26.19,-14 26.19,-5.797 22.652,-2.259 22.652,0.557 20.78,2.429 20.78,5.897 21.316,6.433 31.816,6.433 33.563,8.18 43.84,8.18 44.16,7.86 45.342,7.86 v3(45.367,7.835)
FE_CTRL3: CN2.11 SB5.1 | length 25.3
  Top Layer w0.15: CN2.11@28.73,-14 30.23,-15.5 44.7,-15.5 45.25,-14.95 45.25,-11.25 46.102,-10.398 46.102,-7.399 SB5.1@46.153,-7.348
